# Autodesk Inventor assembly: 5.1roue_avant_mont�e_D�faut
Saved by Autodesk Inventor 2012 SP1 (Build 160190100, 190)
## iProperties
Created: 2011-01
Part Number: 5.1roue_avant_mont�e_D�faut
Document SubType Name: Assembly
Designer: eric
Mass: 293.57 g
Surface Area: 1571.94 cm^2
Volume: 293.57 cm^3
Density: 1 g/cm^3
Author: eric
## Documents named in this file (3)
- D:\Cours\Inventor salle SI\chariot_de_golf_2008\chariot_de_golf_trolem\5.1roue_avant_montee_Defaut.iam
- D:\Cours\Inventor salle SI\chariot_de_golf_2008\chariot_de_golf_trolem\8pneu_Defaut.ipt
- D:\Cours\Inventor salle SI\chariot_de_golf_2008\chariot_de_golf_trolem\8.1jante_Defaut.ipt
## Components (2 placed, 2 different names)
1. 8pneu_Defaut:1
2. 8.1jante_Defaut:1
